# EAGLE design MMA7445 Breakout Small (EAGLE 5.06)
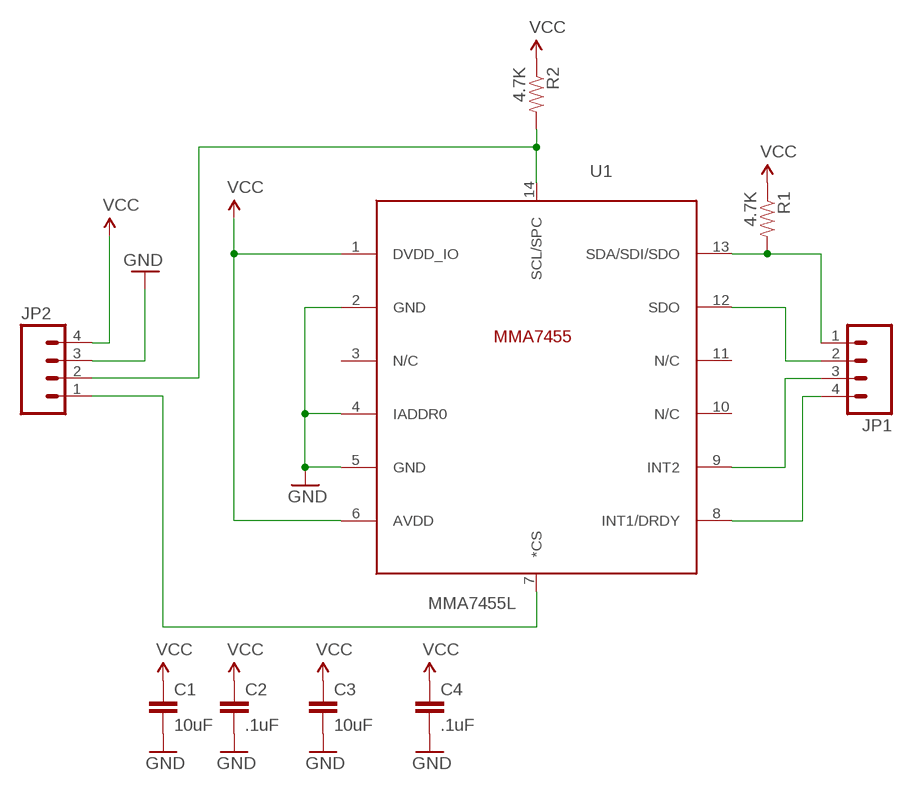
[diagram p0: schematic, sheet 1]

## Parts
C1  10uF  CAP0805  [0805]
C2  .1uF  CAP0805  [0805]
C3  10uF  CAP0805  [0805]
C4  .1uF  CAP0805  [0805]
JP1  M04LOCK  [1X04_LOCK]
JP2  M04LOCK  [1X04_LOCK]
R1  4.7K  RESISTOR  [0805]
R2  4.7K  RESISTOR  [0805]
U1  MMA7455L  [LGA14]

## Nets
GND: C1.2 C2.2 C3.2 C4.2 JP2.3 U1.2(GND) U1.4(IADDR0) U1.5(GND)
N$4: JP1.4 U1.8(INT1/DRDY)
N$5: JP1.3 U1.9(INT2)
N$6: JP1.2 U1.12(SDO)
N$7: JP1.1 R1.2 U1.13(SDA/SDI/SDO)
N$8: JP2.1 U1.7(*CS)
N$9: JP2.2 R2.2 U1.14(SCL/SPC)
VCC: C1.1 C2.1 C3.1 C4.1 JP2.4 R1.1 R2.1 U1.1(DVDD_IO) U1.6(AVDD)
Unconnected: U1.3(N/C) U1.10(N/C) U1.11(N/C)

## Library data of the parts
C1-C4 = SparkFun:CAP: Capacitor
JP1 JP2 = SparkFun:M04: Header 4 Standard 4-pin 0.1" header. Use with straight break away headers (SKU : PRT-00116), right angle break away headers (PRT-00553), swiss pins (PRT-00743), machine pins (PRT-00117), and female headers (PRT-00115). Molex polarized connector foot print use with SKU : PRT-08231 with associated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
R1 R2 = SparkFun:RESISTOR: Resistor
U1 = mylib:MMA7455L: Freescale Digital Ouput Accelerometer

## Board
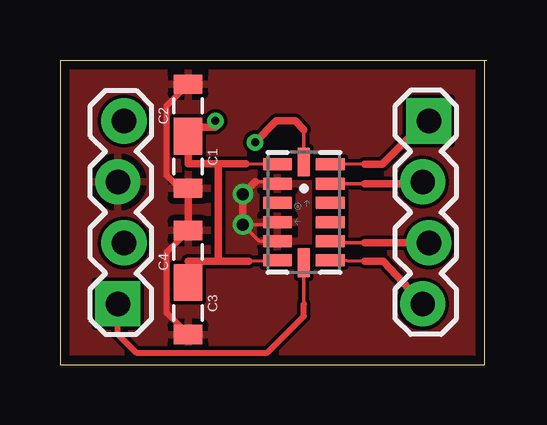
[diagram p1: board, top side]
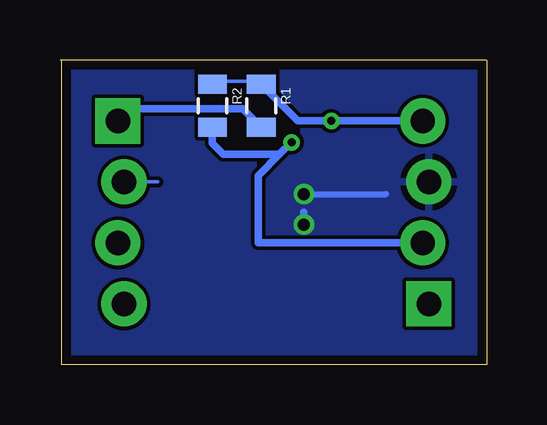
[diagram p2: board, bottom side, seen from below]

Size 17.78 x 12.7 mm. Coordinates in mm from the lower left corner, seen from the top.
Outline: 17.7,12.69 17.7,0 0,0 0,12.69
Outline: 0.01,12.7 17.78,12.7
Copper layers (1*16): Top 0.0356mm / dielectric 1.5011mm / Bottom 0.0356mm
Design rules "LaenPCBOrder": minimum track width 6mil, minimum drill 13mil, track to track 6mil, track to pad 6mil, pad to pad 6mil, via to via 6mil, smd to smd 6mil, copper to edge 15mil, drill to drill 6mil, minimum pad ring 7mil, minimum via ring 7mil, stop-mask expansion 4mil, vias tented up to drill 0mil, thermal gap 10mil

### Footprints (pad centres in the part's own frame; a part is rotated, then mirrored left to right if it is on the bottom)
0805 = smd 0.8 x 1.2: 1 -0.9,0; 2 0.9,0
1X04_LOCK = drill 1.016 pad 1.88 square: 1 0,0.127 | drill 1.016 pad 1.88 round: 2 2.54,-0.127; 3 5.08,0.127; 4 7.62,-0.127
LGA14 = smd 0.5 x 1.2: 1 2,1.1; 2 1.2,1.1; 3 0.4,1.1; 4 -0.4,1.1; 5 -1.2,1.1; 6 -2,1.1; 8 -2,-1.1; 9 -1.2,-1.1; 10 -0.4,-1.1; 11 0.4,-1.1; 12 1.2,-1.1; 13 2,-1.1 | smd 1.2 x 0.5: 7 -2.1,0; 14 2.1,0

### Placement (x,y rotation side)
C1  5.33,8.25 270 top
C2  5.33,10.8 90 top
C3  5.33,2.16 270 top
C4  5.33,4.7 90 top
JP1  15.24,10.16 270 top
JP2  2.54,2.54 90 top
R1  9.4,10.8 270 bottom
R2  11.43,10.8 270 bottom
U1  10.16,6.35 90 top

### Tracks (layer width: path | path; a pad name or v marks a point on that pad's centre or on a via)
GND  (via drill 0.5)
  Top 0.152: C3.2 | 5.33,5.59 C4.2 | U1.2 8.99,7.62 8.13,7.62 | U1.4 8.95,5.84 v7.62,5.84 8.31,5.15 U1.5 | 5.33,11.68 C2.2
  Top 0.254: C3.2 4.45,2.16 4.45,4.7 5.33,5.59 | 5.33,11.68 4.45,10.8 4.45,7.89 4.98,7.36 C1.2
  Top 0.305: C4.2 C1.2 | v7.62,5.84 v7.62,7.11 8.13,7.62
  Bottom 0.254: v7.62,7.11 4.19,7.11
  Bottom 0.305: v7.62,5.84 7.62,6.35
  pour Top: 0,12.7 17.78,12.7 17.78,0 0,0
  pour Bottom: 0,12.7 17.78,12.7 17.78,0 0,0
N$4
  Top 0.152: U1.8 12.7,4.32
  Top 0.305: JP1.4 13.46,4.32 12.7,4.32
N$5
  Top 0.152: 12.7,5.08 11.33,5.08 U1.9
  Top 0.305: 12.7,5.08 JP1.3
N$6
  Top 0.152: U1.12 12.7,7.55 | JP1.2 15.04,7.55
  Top 0.305: 12.7,7.55 15.11,7.55
  Top 0.406: 15.11,7.55 JP1.2
  Bottom 0.152: JP1.2 13.71,7.62
N$7
  Top 0.152: U1.13 12.7,8.38 12.7,8.35 | 15.24,10.16 JP1.1
  Top 0.305: 12.7,8.35 13.43,8.35 15.24,10.16
  Bottom 0.152: 9.4,9.91 R1.2
  Bottom 0.305: 9.4,9.91 10.16,10.67 14.86,10.67 JP1.1
N$8
  Top 0.152: 10.16,2.54 U1.7
  Top 0.254: JP2.1 2.41,1.28 3.19,0.51 8.64,0.51 10.16,2.03 10.16,2.54
N$9  (via drill 0.33)
  Top 0.152: 10.16,9.8 U1.14
  Top 0.305: 10.16,9.8 9.8,10.16 9.02,10.16 v8.13,9.27
  Bottom 0.305: 8.64,8.76 9.53,7.87 9.53,5.08 JP2.2 | 8.64,8.76 v8.13,9.27 | 8.64,8.76 10.97,8.76 11.43,9.22 R2.2
VCC  (via drill 0.33)
  Top 0.152: C3.1 C4.1 5.33,4.32 | 7.87,4.32 U1.6 | C1.1 C2.1 5.33,9.91 | 7.75,8.38 U1.1
  Top 0.305: 5.33,4.32 6.6,4.32 | 6.6,4.32 7.87,4.32 | 6.6,8.38 5.33,8.38 C1.1 | 6.6,8.38 7.75,8.38 | 6.6,4.32 6.6,8.38 | 5.33,9.91 6.48,9.91 v6.48,10.16
  Bottom 0.152: R2.1 11.43,11.81 9.4,11.81 R1.1 9.4,11.68
  Bottom 0.305: 9.4,11.68 7.87,10.16 v6.48,10.16 JP2.4

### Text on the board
tValues: VCC | SDA | SDO | GND | SCL | INT2 | CS | INT1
